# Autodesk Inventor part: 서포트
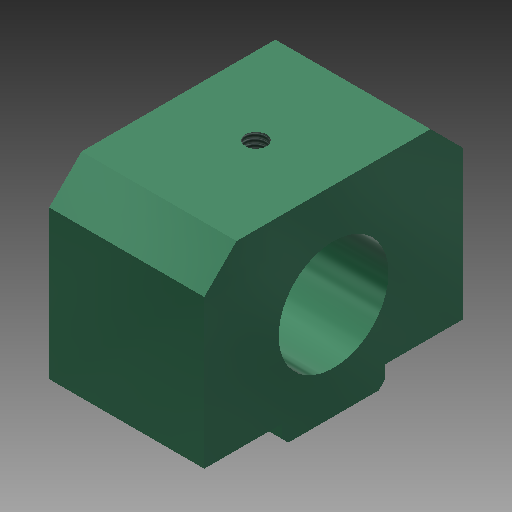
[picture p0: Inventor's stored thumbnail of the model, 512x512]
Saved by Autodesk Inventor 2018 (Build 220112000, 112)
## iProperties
Created: 2019-04
Part Number: 서포트
Material: 알루미늄 6061
Document SubType Name: Modeling
Designer: mduedu
Density: 1 g/cm^3
Appearance: Smooth - Dark Sea Green
Author: mduedu
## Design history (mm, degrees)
sketch "스케치1"
  geometry: L1 (3, 20)-(31, 20); L2 (31, 20)-(31, -20); L3 (31, -20)-(3, -20); L4 (0, -8)-(0, 8); L5 (0, 8)-(3, 8); L6 (3, 8)-(3, 20); L7 (0, 0)-(31, 0); L8 (0, -8)-(3, -8); L9 (3, -8)-(3, -20); 1 further point
  constraints: 18 end point, 3 symmetric about line, 2 horizontal, 2 midpoint, 2 parallel, 2 perpendicular, 1 coincident
  dimensions: "d3" = 31 distance between parallel lines of L4 L2; "d5" = 16 distance of L4.start L4.end; "d6" = 40 distance between parallel lines of L3 L1; "d7" = 3 distance between parallel lines of L4 L9
extrude "돌출1" new body sketch "스케치1" distance "d8" = 24; taper "d9" = 0 deg
chamfer "모따기1" distance "d10" = 5; stored, may be unused: second distance "d11" = 2, angle "d12" = 45 deg
chamfer "모따기2" distance "d13" = 1; stored, may be unused: second distance "d14" = 2, angle "d15" = 45 deg
sketch "스케치2"
  geometry: L1 (7, 0)-(-7, 0) reference; L2 (20, 3)-(8, 3) reference; 3 further points
  constraints: 1 midpoint, 1 vertical alignment
  dimensions: "d24" = 12 distance from line of point (0, 15) L2
hole "구멍1" sketch "스케치2" at (0, 15) diameter "d17" = 17; stored, may be unused: countersink angle "d21" = 90 deg, drill point angle "d23" = 118 deg; dims "d18" = 6, "d19" = 21, "d20" = 3, "d22" = 8
sketch "스케치3"
  geometry: L1 (0, 30)-(0, 0) reference; 3 further points
  constraints: 1 horizontal alignment, 1 midpoint
  dimensions: "d25" = 12 distance from line of point (12, 15) L1
hole "구멍2" sketch "스케치3" at (12, 15) diameter "d26" = 3.242; stored, may be unused: countersink angle "d30" = 90 deg, drill point angle "d32" = 118 deg; dims "d27" = 6, "d28" = 21, "d29" = 3, "d31" = 8
sketch "스케치4"
  geometry: L1 (0, -8)-(24, -8); L2 (24, 0.5)-(24, -16.5) reference; L3 (0, -28)-(0, -23) reference; 4 further points
  constraints: 2 end point, 2 symmetric about line, 1 horizontal, 1 horizontal alignment, 1 midpoint
  dimensions: "d33" = 6 distance from line of point (6, -22) L3; "d34" = 12 distance of point (18, -22) point (6, -22); "d35" = 28 distance of point (6, 6) point (6, -22); "d36" = 14 distance from line of point (6, -22) L1 (derived)
hole "구멍3" sketch "스케치4" at (6, -22), (18, -22), (18, 6), (6, 6) diameter "d37" = 3.242; stored, may be unused: countersink angle "d41" = 90 deg, drill point angle "d43" = 118 deg; dims "d38" = 9, "d39" = 21, "d40" = 3, "d42" = 11
node "솔리드1"
